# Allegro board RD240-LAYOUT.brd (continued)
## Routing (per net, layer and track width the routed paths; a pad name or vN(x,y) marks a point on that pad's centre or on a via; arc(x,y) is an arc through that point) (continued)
LGND: length 528.6
  TOP w0.3: v1(244.3,6.5) 244.88,6.5 R208.1 ; 193.43,130.2 194.01,130.2 194.13,130.32 v1(194.63,130.32) ; R70.1 247.7,11.18 v1(247.7,12.1) ; 233.2,53.42 233.2,52.44 ; 233.2,53.42 232.53,53.42 ; 233.2,53.42 233.21,53.42 233.67,53.88 234.74,53.88 235.1,54.24 v2(235.1,57.45) ; 229.66,68.86 229.87,69.22 v1(230.1,69.55) ; v1(236.73,14.61) 236.73,15.78
  TOP w0.45: R25.1 232.53,53.42 ; 226.95,102.01 226.95,103.31 ; C61.1 227.72,105.4 226.95,104.63 226.95,104.09 ; 236.73,15.78 C818.1
  TOP w0.5: 255.82,9.9 255.82,6.1 ; 255.82,11.9 255.82,17.7
  TOP w0.55: 229.66,68.16 229.66,68.86 ; D29.A 233.2,52.44
  TOP w0.72: 193.43,130.2 R805.1
  TOP w0.92: 226.95,103.31 C88.1 226.95,104.09 ; C89.1 226.95,102.01
  TOP w1: 302.5,88 C6.1 ; C6.1 300.5,90 ; C6.1 300.5,86.85 ; C3.1 292.5,129.5 ; C3.1 291,128 ; C3.1 294,128 ; C5.1 301.5,99 ; C5.1 303.5,100.5 ; C5.1 301.5,102.5 ; 301.5,114.5 C4.1 ; C4.1 304,112.5 ; C4.1 301.5,110.5 ; 220.75,21.82 220.75,24.73 v1(220.05,25.43) ; 278.5,128 C2.1 ; C2.1 280.5,130 ; C2.1 282.5,128
  TOP w1.5: CN9.2 272.46,127.99 ; CN8.2 266.41,128.09
  TOP w1.6: C816.1 220.75,21.82
  TOP w2.3: v3(297.5,32.5) CN7.1 ; v3(297.5,32.5) 302.25,32.5 ; v3(297.5,32.5) 294.05,32.5 ; v3(297.5,32.5) 297.5,37.1 ; CN7.1 303,26 ; CN7.1 297.5,20.85 ; CN7.1 293.1,26 ; v3(281.5,26) v3(281.5,32.5) ; v3(281.5,26) 281.5,22.7 ; v3(281.5,26) 278.3,26 ; v3(281.5,26) 284.6,26 ; v3(281.5,32.5) 277.65,32.5 ; v3(281.5,32.5) 281.5,37.65 ; v3(281.5,32.5) 285,32.5
  CONDUCTIVE2 w0.3: v1(194.63,130.32) 196.09,130.32
  CONDUCTIVE2 w1: CN9.2 272.46,127.02 ; CN9.2 274.21,125.27 ; CN9.2 272.46,123.52 ; CN8.2 266.41,127.02 ; CN8.2 266.41,123.52 ; CN8.2 268.16,125.27 ; C3.1 294.2,128 ; C3.1 292.5,126.3 ; C3.1 290.8,128 ; C3.1 292.5,129.7 ; CN10.2 268.3,16.84 ; CN10.2 271.3,16.84 ; CN10.2 269.8,18.34 ; TP42.1 265.7,5.3 ; TP42.1 267.4,7 ; TP42.1 265.7,8.7 ; TP42.1 264,7 ; C6.1 302.2,88 ; C6.1 300.5,86.3 ; C6.1 298.8,88 ; C6.1 300.5,89.7 ; C5.1 301.5,98.8 ; C5.1 301.5,102.2 ; C5.1 299.8,100.5 ; C5.1 303.2,100.5 ; C2.1 280.5,129.7 ; C2.1 278.8,128 ; C2.1 280.5,126.3 ; C2.1 282.2,128 ; C4.1 301.5,114.2 ; C4.1 301.5,110.8 ; C4.1 303.2,112.5 ; C4.1 299.8,112.5 ; TP41.1 301.3,121.1 ; TP41.1 303,122.8 ; TP41.1 303,119.4
  CONDUCTIVE2 w2.3: CN7.1 v3(297.5,32.5) ; CN7.1 297.5,22.05 ; CN7.1 293.4,26 ; CN7.1 300.4,26 ; v3(297.5,32.5) 301.65,32.5 ; v3(297.5,32.5) 293.75,32.5 ; v3(297.5,32.5) 297.5,36.9 ; v3(281.5,26) v3(281.5,32.5) ; v3(281.5,26) 281.5,22.1 ; v3(281.5,26) 277.05,26 ; v3(281.5,26) 285.4,26 ; v3(281.5,32.5) 281.5,37.25 ; v3(281.5,32.5) 277.6,32.5 ; v3(281.5,32.5) 285.75,32.5
  CONDUCTIVE5 w0.3: v1(194.63,130.32) 196.87,130.32
  CONDUCTIVE5 w1: CN10.2 271.3,16.84 ; CN10.2 268.3,16.84 ; CN10.2 269.8,18.34 ; TP42.1 265.7,5.3 ; TP42.1 264,7 ; TP42.1 267.4,7 ; TP42.1 265.7,8.7 ; C2.1 280.5,126.3 ; C2.1 282.2,128 ; C2.1 280.5,129.7 ; C2.1 278.8,128 ; C4.1 301.5,114.2 ; C4.1 299.8,112.5 ; C4.1 301.5,110.8 ; C4.1 303.2,112.5 ; TP41.1 303,119.4 ; TP41.1 303,122.8 ; TP41.1 304.45,121.1 ; TP41.1 301.3,121.1 ; C3.1 292.5,126.3 ; C3.1 292.5,129.7 ; C3.1 290.8,128 ; C3.1 294.2,128 ; C6.1 300.5,86.3 ; C6.1 298.8,88 ; C6.1 300.5,89.7 ; C6.1 302.2,88 ; C5.1 301.5,98.8 ; C5.1 299.8,100.5 ; C5.1 303.2,100.5 ; C5.1 301.5,102.2 ; CN9.2 272.46,123.52 ; CN9.2 272.46,127.02 ; CN9.2 274.21,125.27 ; CN8.2 266.41,123.52 ; CN8.2 268.16,125.27 ; CN8.2 266.41,127.02
  CONDUCTIVE5 w2.3: CN7.1 297.5,20.65 ; CN7.1 301.3,26 ; CN7.1 292.3,26 ; CN7.1 v3(297.5,32.5) ; v3(281.5,32.5) 276.65,32.5 ; v3(281.5,32.5) 284.95,32.5 ; v3(281.5,32.5) v3(281.5,26) ; v3(281.5,32.5) 281.5,38.35 ; v3(297.5,32.5) 297.5,37.1 ; v3(297.5,32.5) 293.05,32.5 ; v3(297.5,32.5) 301.25,32.5 ; v3(281.5,26) 281.5,21.95 ; v3(281.5,26) 285.35,26 ; v3(281.5,26) 278.05,26
  BOTTOM w0.3: 234.38,5.75 235.47,5.75 R829.1 ; 235.32,5.72 234.2,5.72 ; 231.56,10.75 231.95,10.75 v1(232.2,11) ; v1(245.25,68.95) 245.25,69.67 R22.1 ; v1(227.53,100.01) v1(226.76,100.01) 226.76,101.66 D26.A ; R43.1 259.27,14.5 v1(258.4,14.5) 257.68,14.5 257.4,14.22 ; 234.38,8.78 235.38,8.78 ; 235.68,5.72 v1(236.54,5.72) ; 235.68,8.72 v1(236.54,8.72) ; v1(260.2,5.4) 259.2,5.4 ; 260,16.2 v1(261,16.2) ; 235.32,8.72 234.2,8.72
  BOTTOM w0.45: 259.2,5.4 259.02,5.4 ; IC12.2 231.04,10.41 C104.1 231.56,10.75 ; 234.2,8.78 234.38,8.78 ; R45.1 260,16.2 ; 235.32,8.72 R821.1 235.68,8.72 ; 235.32,5.72 R829.1 235.68,5.72 ; R825.1 234.38,5.75 ; v1(268.1,35.3) 268.11,35.31 268.11,36.55
  BOTTOM w0.5: T4.3 215.6,44.42 ; TP42.1 266.75,5.95 ; R21.1 237.38,104.55 v1(235.3,104.55) ; CN10.2 269.8,17.85 ; v1(220.05,25.43) 218.28,27.2 R9.1 ; v1(244.3,9.3) R66.1 ; v1(244.3,6.5) R64.1 ; v2(235.1,122.6) 233.6,122.6 233.15,122.15 D27.A ; v1(253.7,5.1) R54.1
  BOTTOM w0.825: IC8.4 268.11,36.55
  BOTTOM w1: C3.1 292.5,129.5 ; C3.1 292.5,126.3 ; C3.1 294,128 ; C3.1 291,128 ; 214.85,16 215.9,16 R812.1 ; C6.1 300.5,86 ; C6.1 300.5,90 ; C6.1 298.5,88 ; C6.1 302.5,88 ; C5.1 301.5,98.5 ; C5.1 301.5,102.5 ; C5.1 300,100.5 ; C5.1 303.5,100.5 ; C2.1 282.5,128 ; C2.1 278.5,128 ; C2.1 280.5,130 ; C2.1 280.5,126 ; C4.1 301.5,110.5 ; C4.1 303.5,112.5 ; C4.1 300,112.5 ; C4.1 301.5,114.5
  BOTTOM w2.3: CN7.1 292.3,26 ; CN7.1 v3(297.5,32.5) ; CN7.1 297.5,21.4 ; CN7.1 302,26 ; v3(281.5,26) 278.8,26 ; v3(281.5,26) v3(281.5,32.5) ; v3(281.5,26) 281.5,21.7 ; v3(281.5,26) 286.05,26 ; v3(297.5,32.5) 301.3,32.5 ; v3(297.5,32.5) 293.65,32.5 ; v3(297.5,32.5) 297.5,36.6 ; v3(281.5,32.5) 281.5,35.8 ; v3(281.5,32.5) 278.95,32.5 ; v3(281.5,32.5) 286.15,32.5
  vias: v1(232.92,2.65) v1(233.35,60.85) v1(234.6,60.85) v1(235.2,17.02) v1(249.34,17.25) v1(252.9,17.3) v1(257,11.2) v1(260.05,8.9) v1(269.5,35.3) v1(304.5,80) v1(304.5,74.6) v1(304.5,70) v1(304.5,65) v1(304.5,60) v1(304.5,55) v1(304.5,51.8) v1(304.5,48.55) v2(227.85,89.85) v2(227.85,87.75) v2(229.95,89.85) v2(229.95,87.75) v2(229.95,85.65) v2(235.05,128.5) v2(235.3,114) v2(235.3,111.9) v2(235.3,109.8) v2(235.3,67.35) v2(235.3,65.25) v2(235.3,63.15) v2(235.4,81.8) v2(235.4,79.7) v2(235.4,76.7) v2(236.25,130.6) v2(236.35,59.15) v2(236.7,68.95) v2(237.15,128.5) v2(237.2,122.6) v2(237.4,114) v2(237.4,111.9) v2(237.4,109.8) v2(237.5,81.8) v2(237.5,79.7) v2(237.5,76.7) v2(237.71,57.41) v2(237.77,65.27) v2(237.8,63.15) v2(238.35,130.6) v2(238.8,68.95) v2(239.3,128.5) v2(239.5,116.1) v2(239.5,114) v2(239.5,111.9) v2(239.5,109.8) v2(239.6,81.8) v2(239.6,79.7) v2(240.45,130.6) v2(240.9,68.95) v2(241.7,79.7) v2(242.55,130.6) v2(262,130.5) v2(271,130.5) v2(273,130.5) v2(273,128.5) v2(275,130.5) v2(275.1,36.6) v2(275.1,33.6) v2(275.1,30.6) v2(275.1,27.6) v2(275.1,24.6) v2(275.1,21.6) v2(275.1,18.6) v2(275.1,15.6) v2(277.1,35.1) v2(277.1,32.1) v2(277.1,29.1) v2(277.1,26.1) v2(277.1,23.1) v2(277.1,20.1) v2(277.1,17.1) v2(279.1,42.4) v2(279.1,39.4) v2(279.1,21.6) v2(279.1,18.6) v2(279.1,15.6) v2(281.1,40.9) v2(281.1,37.9) v2(281.1,20.1) v2(281.1,17.1) v2(283.1,42.4) v2(283.1,39.4) v2(283.1,21.6) v2(283.1,18.6) v2(283.1,15.6) v2(284,130.5) v2(285.1,40.9) v2(285.1,37.9) v2(285.1,20.1) v2(285.1,17.1) v2(286,130.5) v2(286,128.5) v2(287.1,42.4) v2(287.1,39.4) v2(287.1,36.4) v2(287.1,21.6) v2(287.1,18.6) v2(287.1,15.6) v2(288,130.5) v2(289.1,40.9) v2(289.1,37.9) v2(289.1,20.1) v2(289.1,17.1) v2(291.1,39.4) v2(291.1,36.4) v2(291.1,21.6) v2(291.1,18.6) v2(291.1,15.6) v2(293.1,40.9) v2(293.1,37.9) v2(293.1,20.1) v2(293.1,17.1) v2(295.1,42.4) v2(295.1,39.4) v2(295.1,36.4) v2(295.1,21.6) v2(295.1,18.6) v2(295.1,15.6) v2(297.1,40.9) v2(297.1,37.9) v2(297.1,20.1) v2(297.1,17.1) v2(297.5,130.5) v2(299,124.4) v2(299.1,42.4) v2(299.1,39.4) v2(299.1,21.6) v2(299.6,121.12) v2(299.9,118.8) v2(301.1,40.9) v2(301.1,37.9) v2(301.1,34.9) v2(301.1,31.9) v2(301.1,28.9) v2(301.1,25.9) v2(301.1,22.9) v2(301.92,124.4) v2(302,118) v2(302,104.5) v2(302,95.5) v2(302,93.5) v2(302,91.5) v2(302,89.5) v2(303.1,39.4) v2(303.1,36.4) v2(303.1,33.4) v2(303.1,30.4) v2(303.1,27.4) v2(303.1,24.4) v2(304,118) v2(304,116) v2(304,106.5) v2(304,104.5) v2(304,102.5) v2(304,93.5) v2(304,91.5) v2(304,89.5)
OUTA1: length 194.6
  TOP w0.3: v1(135.4,121.1) TP38.1 ; 141.66,116.8 141.3,116.8 141.1,117 v1(140.6,117)
  TOP w0.45: 141.66,116.8 141.78,116.8
  CONDUCTIVE3 w0.2: v1(140.6,117) 141.71,117 143.51,115.2 143.51,103 138.18,97.66 138.18,86.11 139.95,84.33 154.56,84.33 163.7,75.18 166.88,75.18 173.3,68.76 173.3,12.65 175.95,10 212.12,10 215.15,6.97 v1(216.97,6.97) ; v1(140.6,115.7) 139.9,116.4 139.9,117.8 136.6,121.1 v1(135.4,121.1)
  BOTTOM w0.5: IC12.14 219.14,9.14 v1(216.97,6.97)
OUTA2: length 47.8
  TOP w0.3: v1(247.8,14.78) 245.34,14.78 241.1,10.54 v1(241.1,9.62) ; v1(265.4,3.5) TP34.1
  CONDUCTIVE3 w0.2: v1(247.8,14.78) 248.28,14.78 249.94,13.12 249.94,8.76 251.59,7.11 259.54,7.11 263.15,3.5 v1(265.4,3.5)
  BOTTOM w0.3: 234.02,9.62 233.17,9.62 R819.1 ; 238.6,9.62 v1(241.1,9.62) ; 230.2,9.14 231.66,9.14 ; IC10.22 v1(247.8,14.78) ; 237.4,9.62 234.38,9.62
  BOTTOM w0.45: 231.66,9.14 R819.2 ; R816.2 238.6,9.62 ; 234.38,9.62 R817.2 234.02,9.62 ; R816.1 237.4,9.62
  BOTTOM w0.55: IC12.3 230.2,9.14
OUTB1: length 201.4
  TOP w0.3: v1(129.1,121.1) TP39.1 ; 141.7,113.4 141.34,113.4 141.14,113.6 v1(140.6,113.6)
  TOP w0.45: 141.7,113.4 141.78,113.4
  CONDUCTIVE3 w0.2: v1(140.6,112.3) 139.5,113.4 139.5,117.6 138.2,118.9 131.3,118.9 v1(129.1,121.1) ; v1(215.79,6.12) 214.99,6.12 211.56,9.55 175.5,9.55 172.7,12.35 172.7,68.47 166.62,74.55 163.19,74.55 154.05,83.69 139.53,83.69 137.59,85.64 137.59,97.83 143,103.24 143,112.21 141.61,113.6 v1(140.6,113.6)
  BOTTOM w0.5: IC12.13 219.17,7.87 217.42,6.12 v1(215.79,6.12)
OUTB2: length 37
  TOP w0.3: v1(247.1,14.12) 245.66,14.12 241.9,10.36 241.9,8.67 v1(241.1,7.87) ; v1(252,3.5) TP35.1
  CONDUCTIVE3 w0.2: v1(252,3.5) 249.17,6.33 249.17,13.15 248.2,14.12 v1(247.1,14.12)
  BOTTOM w0.3: IC10.21 v1(247.1,14.12) ; 235.68,7.87 237.4,7.87 ; 232.87,7.87 235.32,7.87 ; 238.6,7.87 v1(241.1,7.87) ; 230.2,7.87 231.66,7.87
  BOTTOM w0.45: 235.32,7.87 R821.2 235.68,7.87 ; R820.2 238.6,7.87 ; R823.1 232.87,7.87 ; 231.66,7.87 R823.2 ; 237.4,7.87 R820.1
  BOTTOM w0.55: IC12.4 230.2,7.87
OUTC1: length 120.5
  TOP w0.3: R113.1 156.82,66.55 157.83,66.55 159.06,67.78 162.9,67.78 v1(163.38,68.25)
  CONDUCTIVE3 w0.2: v1(216.28,4.95) 215.26,4.95 211.62,8.6 174.6,8.6 171.45,11.75 171.45,35.12 163.38,43.2 v1(163.38,68.25)
  BOTTOM w0.5: v1(216.28,4.95) 216.68,5.35 217.9,5.35 219.15,6.6 IC12.12
OUTC2: length 44.8
  TOP w0.3: v1(258.7,3.5) TP36.1 ; v1(247.8,13.47) 245.94,13.47 242.59,10.12 242.59,8.09 v1(241.1,6.6)
  CONDUCTIVE4 w0.3: v1(258.7,3.5) 257.63,2.43 243.8,2.43 242.65,3.58 242.65,5.05 v1(241.1,6.6)
  BOTTOM w0.3: IC10.20 v1(247.8,13.47) ; 232.87,6.6 234.02,6.6 ; 230.2,6.6 231.66,6.6 ; 234.38,6.6 237.4,6.6 ; 238.6,6.6 v1(241.1,6.6)
  BOTTOM w0.45: R827.1 232.87,6.6 ; 231.66,6.6 R827.2 ; 237.4,6.6 R824.1 ; 234.02,6.6 R825.2 234.38,6.6 ; R824.2 238.6,6.6
  BOTTOM w0.55: IC12.5 230.2,6.6
OUTD1: length 133.7
  TOP w0.3: v1(162.88,69.4) 162.88,68.83 162.43,68.38 158.81,68.38 158.01,67.58 157.24,67.58
  TOP w0.45: R112.1 157.24,67.58
  CONDUCTIVE3 w0.2: v1(217.9,4.35) 216.89,4.35 216.28,3.74 215.51,3.74 211.15,8.1 174.1,8.1 170.75,11.45 170.75,34.95 162.63,43.07 162.63,69.16 v1(162.88,69.4)
  CONDUCTIVE4 w0.2: v1(152.8,76.15) 152.8,74.13 155.85,71.08 159.45,71.08 160.78,69.75 v1(160.78,69.1)
  BOTTOM w0.5: IC12.11 219.23,5.33 218.25,4.35 v1(217.9,4.35)
OUTD2: length 30.4
  TOP w0.3: v1(247.1,12.82) 246.25,12.82 243.2,9.77 243.2,6.97 v1(241.1,4.88) 244.38,1.6 246,1.6
  TOP w2.1: 246,1.6 TP37.1
  BOTTOM w0.3: 230.2,5.33 231.66,5.33 ; 235.32,4.88 233.15,4.88 R831.1 ; 238.6,4.88 v1(241.1,4.88) ; IC10.19 v1(247.1,12.82) ; 235.68,4.88 237.4,4.88
  BOTTOM w0.45: 235.32,4.88 R829.2 235.68,4.88 ; R828.2 238.6,4.88 ; 231.66,5.33 R831.2 ; 237.4,4.88 R828.1
  BOTTOM w0.55: IC12.6 230.2,5.33
OUTE: length 131.5
  TOP w0.3: v1(251,12) 251,19.73 250.55,20.18 250.55,22.36
  TOP w2.1: 250.55,22.36 TP23.1
  CONDUCTIVE4 w0.2: v1(251,12) 251,13.92 246.52,18.4 232.05,18.4 225.65,24.8 225.65,52.37 230.75,57.47 230.75,65.65 v1(231.7,66.6) 231.05,67.25 229.45,67.25 228.25,68.45 228.25,84.1 225.25,87.1 225.25,88.55 235.25,98.55 v1(235.25,103.2)
OUTF: length 135.2
  TOP w0.3: 244.7,22.31 244.7,19.27 249.49,14.48 249.49,12.26 v1(251,10.75)
  TOP w2.1: 244.7,22.31 TP24.1
  CONDUCTIVE4 w0.2: v1(234.2,103.9) 234.2,98.1 224.85,88.75 224.85,86.9 227.85,83.9 227.85,68.05 v1(229.3,66.6) 230.35,65.55 230.35,57.73 225.25,52.63 225.25,24.6 231.85,18 246.29,18 250.06,14.22 250.03,14.19 250.03,11.72 v1(251,10.75)
PN: length 476.1
  TOP w0.3: v1(140.6,118.2) 141.6,118.2 ; v1(127.8,57.1) 126.4,57.1 ; v1(140.6,114.6) 140.8,114.8 141.6,114.8 ; v1(155.7,50.9) 156.7,50.9
  TOP w0.45: 141.6,114.8 141.78,114.8 ; C35.1 151.2,49.3 150.9,49.6 v1(150.3,49.6) ; 156.7,50.9 R71.1 ; v1(130.4,51.6) 133.18,51.6 ; 141.6,118.2 141.78,118.2 ; C62.1 v1(147.9,53.6) ; 126.4,57.1 R73.1
  TOP w0.5: v1(178.44,123.95) 178.44,123.64 177.95,123.15 R224.1 ; v1(150.3,51.9) 149.57,51.9 ; v1(130.9,70.5) 130.62,70.78 129.6,70.78 ; R223.1 173.53,99.2 v1(172.64,99.2) ; R225.1 83.08,129.72 v1(82.87,129.93) ; v1(150.3,49.6) 149.57,49.6 ; R221.1 167.3,47.17
  TOP w0.92: 149.57,51.9 C82.1 ; 149.57,49.6 C83.1
  TOP w1: 203.45,16 198.87,16 C800.1
  CONDUCTIVE2 w1: 203.45,16 203.45,14.45 ; 203.45,16 201.9,16 ; 203.45,16 205,16 ; Q6.S v1(166.28,129.8) 166.28,129.5 ; Q6.S 168.21,131.3 ; Q6.S 164.82,131.3 ; IC20.1 84.75,71.29 ; C800.1 187.56,6.38 ; C800.1 189.25,4.69 ; C800.1 189.25,8.07 ; C800.1 190.94,6.38 ; C7.1 133.02,26.8 ; C7.1 129.5,30.14 ; C7.1 129.5,23.46 ; C7.1 125.78,26.8 ; D3.4 124.7,129.32 ; D3.4 122.71,130.98 ; D3.4 124.7,132.43 ; D3.4 126.87,130.98 ; Q2.S v1(142.82,63.65) 142.82,63.95 ; Q2.S 144.25,62.15 ; Q2.S 141.02,62.15 ; Q2.S 142.82,60.35 ; Q4.S 159.92,85.7 ; Q4.S 158.12,87.5 ; Q4.S 161.24,87.5 ; Q4.S v1(159.92,89) 159.92,89.3 ; Q1.S 111.62,60.35 ; Q1.S v1(111.62,63.65) 111.62,63.95 ; Q1.S 109.82,62.15 ; Q1.S 112.87,62.15 ; 109.3,70.2 T3.2 111.1,68.4 ; C1.1 160.65,28.49 ; C1.1 157.03,25.15 ; C1.1 160.65,21.66 ; C1.1 164.56,25.15 ; 134.6,68.4 T2.2 132.8,70.2 ; TP45.1 177.9,3.7 ; TP43.1 125,3.6
  CONDUCTIVE3 w0.2: v1(105.6,84.9) 106.7,83.8 121.4,83.8 122.75,82.45 122.75,66.5 124.6,64.65 124.6,53.3 132.28,45.62 149.05,45.62 152.6,42.08 152.6,28.6 153.6,27.6 153.6,4.15 v1(152.8,3.35) ; v1(126.6,82.4) 126.45,81.94 126.45,60.15 128.8,57.8 131.9,57.8 142.3,47.4 149.2,47.4 156.2,40.4 156.2,30.05 156.68,29.57 156.68,4.98 v1(155.7,4)
  CONDUCTIVE5 w1: D3.4 124.7,132.38 ; D3.4 122.28,130.98 ; D3.4 124.7,129.21 ; D3.4 126.68,130.98 ; 132.8,70.2 T2.2 134.6,68.4 ; TP45.1 177.9,3.7 ; Q6.S v1(166.28,129.8) 166.28,129.5 ; Q6.S 164.92,131.3 ; Q6.S 168.36,131.3 ; C1.1 160.65,28.49 ; C1.1 160.65,21.81 ; C1.1 163.99,25.15 ; C1.1 157.31,25.15 ; 159.92,89.3 v1(159.92,89) Q4.S ; C7.1 129.5,23.46 ; C7.1 132.84,26.8 ; C7.1 126.16,26.8 ; C7.1 129.5,30.14 ; Q2.S v1(142.82,63.65) 142.82,63.95 ; Q2.S 141.02,62.15 ; Q2.S 142.82,60.35 ; Q2.S 144.15,62.15 ; 203.45,16 205,16 ; 203.45,16 203.45,14.45 ; 203.45,16 201.9,16 ; Q4.S 158.12,87.5 ; Q4.S 159.92,85.7 ; Q4.S 161.35,87.5 ; C800.1 189.25,4.69 ; C800.1 187.56,6.38 ; C800.1 189.25,8.07 ; C800.1 190.94,6.38 ; Q1.S 111.62,60.35 ; Q1.S 113,62.15 ; Q1.S 109.82,62.15 ; Q1.S v1(111.62,63.65) 111.62,63.95 ; TP43.1 125,3.6 ; 109.3,70.2 T3.2 111.1,68.4 ; IC20.1 84.91,71.45
  BOTTOM w0.3: C1.1 156.6,25.15 ; 214.9,4.96 214.3,4.96 213.53,4.19 211.02,4.19 ; C7.1 126.7,24 ; v1(105.6,84.9) 105.12,85.38 103.81,85.38 103.54,85.65 103.54,86.32
  BOTTOM w0.45: v1(187.71,13.24) 187,13.95 ; R806.1 R807.1 ; 214.9,4.96 C67.1
  BOTTOM w0.5: 219.94,10.4 v1(221.54,10.4) ; TP43.1 125,9.3 133,17.3 135.68,17.3
  BOTTOM w0.55: IC11.2 211.02,4.19
  BOTTOM w0.895: 103.54,86.32 R7.1
  BOTTOM w1: IC20.1 84,70.54 ; TP45.1 179.4,2 ; C800.1 189.25,4.85
  BOTTOM w1.405: 135.68,17.3 R179.1
  BOTTOM w1.5: 203.45,16 204.85,16
  vias: v1(110.62,63.65) v1(112.62,63.65) v1(120.4,52.8) v1(140.4,3.45) v1(141.1,110.5) v1(141.1,109.2) v1(141.1,107.9) v1(141.82,63.65) v1(142.75,98.05) v1(142.75,96.8) v1(143.82,63.65) v1(144.4,3.25) v1(144.7,51.8) v1(145.9,7.55) v1(146.5,13.15) v1(151.29,14.99) v1(151.7,9.85) v1(153.5,75.45) v1(155.9,112.1) v1(155.9,110.8) v1(158.92,89) v1(160.92,89) v1(161.82,69.1) v1(164.18,69.28) v1(165.28,129.8) v1(166.1,69.85) v1(166.1,68.6) v1(167.28,129.8) v1(167.3,47.2) v1(175.18,26.9) v1(175.18,26.15) v1(175.26,18.29) v1(175.26,16.76) v1(208.5,4.2) v1(218.28,2.08)
SIG6: length 54.1
  TOP w0.3: 120.69,124.85 119.65,124.85 117.2,127.3 D3.3
  TOP w1.2: 120.69,124.85 D9.A
  BOTTOM w1: IC20.3 92.11,49.47 ; C33.1 74.39,125.15 ; R138.1 98.52,50.48
  BOTTOM w1.5: C64.2 117.22,11.9
  BOTTOM w5: D3.3 117.2,117.9 117.9,117.2 117.9,102.5 ; L12.1 104.88,32.2 ; 109.29,123.09 109.29,130.97
  vias: v1(76.71,93.09) v1(129.1,63.81) v1(130.1,63.81) v1(131.1,63.81) v1(160.3,63.81) v1(161.3,63.81)
SIG15: length 1.3
  BOTTOM w0.3: 129,84.28 129,83.6
  BOTTOM w0.55: D12.A 129,84.28
SIG18:
  vias: v1(147.26,63.65) v1(148.26,63.65) v1(149.26,63.65)
SIG20: length 2.1
  BOTTOM w0.3: 105.92,84.05 105.92,83.28 106.4,82.8 106.8,82.8
  BOTTOM w0.45: C36.2 105.92,84.05 ; 106.8,82.8 R85.1
SIG22:
  vias: v1(116.06,63.65) v1(117.06,63.65) v1(118.06,63.65)
SIG23:
  vias: v1(153.7,63.65)
SIG27: length 6.8
  TOP w0.3: Q1.G 122.5,55.67
  TOP w1.17: 122.5,55.67 FB2.2
  vias: v1(122.5,63.65)
SIG47: length 6.2
  BOTTOM w0.35: 149.29,14.47 148.5,14.47 147.5,15.47 R93.2 ; 147.74,11.91 148.67,11.91 149.4,12.64 149.4,13.44
  BOTTOM w0.45: C41.2 149.4,13.44 ; 149.29,14.47 C41.1
  BOTTOM w0.72: 147.74,11.91 C40.2
SIG0052: length 53.8
  TOP w0.3: v1(246.8,122.24) 246.04,123 241.94,123 ; v1(233.45,120.3) 233.45,119.16 233.47,118.79
  TOP w0.5: 233.47,118.79 Q13.4
  TOP w2.1: 241.94,123 TP19.1
  CONDUCTIVE3 w0.3: v1(246.8,122.24) 244.06,119.5 234.25,119.5 v1(233.45,120.3)
  CONDUCTIVE4 w0.6: v1(233.45,120.3) v1(233.45,113.6) 233.45,109.75 234.9,108.3 236.85,108.3 v1(237.15,108) 237.15,102.8 v1(239,100.95)
  BOTTOM w0.3: 233.44,101.8 234.73,101.8 ; R213.2 238.72,101.8 R21.2 ; 234.5,99.5 236.11,99.5 ; 239,99.89 v1(239,100.95) 239,101.9
  BOTTOM w0.45: 239,101.9 R21.2
  BOTTOM w0.8: 233.44,101.8 D54.A 233.22,101.8
  BOTTOM w0.92: 236.11,99.5 R20.1 ; R20.2 239,99.89 ; 234.73,101.8 R213.1
  BOTTOM w1.1: D53.C 234.5,99.5
SIG53: length 1.1
  BOTTOM w0.45: R176.2 155.5,5.56 R101.2
SIG0053: length 42.8
  TOP w0.3: v1(233.5,126.3) 233.47,125.89 233.47,125.42 ; v1(234.7,131.05) 234.44,131.31 233.88,131.31 ; v1(213.1,129.6) TP21.1
  TOP w0.5: Q12.4 233.47,125.42 ; Q11.4 233.88,131.31
  CONDUCTIVE4 w0.2: v1(213.1,129.6) 215.05,131.55 234.2,131.55 v1(234.7,131.05)
  CONDUCTIVE4 w0.6: v1(238.3,121.3) 234.35,121.3 233.5,122.15 v1(233.5,126.3) 233.5,129.85 v1(234.7,131.05)
  BOTTOM w0.3: v1(233.5,126.3) 233.5,126.9 233.47,126.92 Q25.4
  BOTTOM w0.5: Q25.4 233.8,127.5
SIG54: length 1.1
  BOTTOM w0.45: R175.2 R102.2
SIG0054: length 38.4
  TOP w0.3: 233.47,81.39 233.47,81.95 233.22,82.2 v1(231.6,82.2)
  TOP w0.5: 233.47,81.39 Q7.4
  CONDUCTIVE4 w0.6: v1(225.95,87.95) 225.95,87.85 v1(231.6,82.2) 231.6,80.4 233.87,78.13 v1(235.37,78.13) 242.62,78.13 v1(243.85,76.9) 244.9,75.85 244.9,69.89 v1(243.96,68.95)
  BOTTOM w0.3: v1(225.95,87.95) 225.97,88.36 225.97,89.11 ; v1(235.37,78.13) 234.83,78.13 234.09,77.39 233.72,77.39
  BOTTOM w0.5: Q8.4 225.97,89.11
SIG0055: length 60.7
  TOP w0.3: 233.47,75.39 233.5,75.76 v1(233.5,76.25) ; v1(233.5,54.75) 232.14,54.75 231.5,54.11 231.5,53.45 ; 231.32,53.42 v1(229.55,53.42)
  TOP w0.45: 231.32,53.42 R25.2 231.5,53.45
  TOP w0.5: 233.47,75.39 Q27.4
  CONDUCTIVE4 w0.6: v1(233.5,54.75) 233.5,58.05 v1(236.25,60.8) 236.25,61.4 235.75,61.9 234.75,61.9 234.05,62.6 234.05,69.05 235.25,70.25 242.8,70.25 v1(243.85,71.3) 243.85,72.35 242.15,74.05 234.6,74.05 233.5,75.15 v1(233.5,76.25)
  BOTTOM w0.3: 228,52.03 228,52.77 228.65,53.42 v1(229.55,53.42) ; 233.92,61.8 235.25,61.8 v1(236.25,60.8) ; 228,47.64 228,49.02 ; 230.3,48.98 230.3,47.37 ; v1(233.5,54.75) 233.47,55.16 233.47,55.66 ; 228.61,51.95 229.91,51.95
  BOTTOM w0.5: Q9.4 233.47,55.66
  BOTTOM w0.55: Q10.4 233.92,61.8
  BOTTOM w0.8: D58.A 228,47.64
  BOTTOM w0.92: R24.1 230.3,48.98 ; 228.61,51.95 R215.2 228,52.03 ; 229.91,51.95 R24.2 ; 228,49.02 R215.1
  BOTTOM w1.1: 230.3,47.37 D57.C
SIG82:
  vias: v1(155.4,129.8)
SIG86: length 2.2
  BOTTOM w0.3: 136.25,5.76 137.98,5.76
  BOTTOM w0.45: R120.2 136.25,5.76
  BOTTOM w1.2: 137.98,5.76 D49.C
SIG91: length 2.3
  TOP w0.92: C85.2 170.2,71.25
  BOTTOM w0.3: v1(165.1,71.88) 165.1,72.29 165.05,73.11
  BOTTOM w1.1: 165.05,73.11 D17.A
SIG95:
  vias: v1(153.2,108.8)
SIG116: length 25
  CONDUCTIVE4 w0.6: v1(233.5,47.81) 233.5,53.45 232,54.95 232,65.65 v1(232.95,66.6)
  BOTTOM w0.3: v1(233.5,47.81) 233.5,46.36 232.14,45 230.45,45
  BOTTOM w0.8: D57.A 230.45,45
SIG117:
  vias: v1(228.95,69.55)
SIG121: length 1.7
  TOP w0.45: 229.66,62.28 229.66,61.31 229.68,61.3
  TOP w0.55: 229.66,63.04 229.66,62.28
SIG124: length 4.2
  TOP w0.3: 229.18,99.83 229.18,100.92 C89.2
  TOP w0.45: 229.18,99.83 229.18,99.65 ; 229.65,102.01 229.65,103.31
  TOP w0.92: 229.65,103.31 C88.2 ; C89.2 229.65,102.01
SIG126: length 9.9
  BOTTOM w0.3: 232.1,99.64 232.1,101.05 D54.C ; 229.66,102.7 229.95,102.7 230.2,102.95 v1(233.15,102.95) ; 228.95,102.51 228.95,102.1 229.25,101.8 230.57,101.8
  BOTTOM w0.55: 228.95,102.51 D26.C 229.66,102.7
  BOTTOM w0.8: D53.A 232.1,99.64
  BOTTOM w1.1: 231.22,101.8 230.57,101.8
SIG127: length 9.6
  CONDUCTIVE4 w0.6: v1(231.85,113.6) 231.85,105.75 v1(233.1,104.5)
SIG135: length 1.8
  TOP w2: TP30.1 219.9,129.6
SIG136: length 84.2
  TOP w0.3: 286.1,78.98 v1(286.1,80) ; 273.1,78.98 v1(273.1,80) ; 279.6,78.98 v1(279.6,80) ; v1(268.1,46.15) 268.1,47.6 268.7,48.2 270.27,48.2 ; 292.6,78.98 v1(292.6,80) ; 299.1,78.98 v1(299.1,80)
  TOP w0.5: Q17.4 286.1,78.98 ; Q15.4 299.1,78.98 ; Q18.4 279.6,78.98 ; Q16.4 292.6,78.98 ; Q19.4 273.1,78.98
  TOP w2.1: 270.27,48.2 TP28.1
  CONDUCTIVE4 w0.2: v1(299.1,80) v1(292.6,80) v1(286.1,80) v1(279.6,80) v1(273.1,80) 271.2,78.11 271.2,49.25 v1(268.1,46.15)
  BOTTOM w0.3: v1(286.1,80) 285.9,79.81 285.9,78.98 ; v1(292.6,80) 292.4,79.81 292.4,78.98 ; v1(299.1,80) 298.9,79.81 298.9,78.98 ; v1(279.6,80) 279.4,79.81 279.4,78.98 ; 272.9,78.98 272.9,79.81 v1(273.1,80)
  BOTTOM w0.45: v1(268.1,46.15) R6.2 ; 268.1,43.69 268.1,43.15 268.11,42.64
  BOTTOM w0.5: 279.4,78.98 Q23.4 ; 272.9,78.98 Q24.4 ; 285.9,78.98 Q22.4 ; 292.4,78.98 Q21.4 ; 298.9,78.98 Q20.4
  BOTTOM w0.72: R6.1 268.1,43.69
  BOTTOM w0.825: 268.11,42.64 IC8.5
SIG138: length 17.9
  TOP w0.3: v1(206.5,129.6) TP27.1
  CONDUCTIVE3 w0.2: v1(206.5,129.6) 207.13,128.97 ; R77.2 242.51,125.61
  BOTTOM w2: 234.85,124.6 242.4,124.6 ; 237.05,106.1 243.2,106.1
SIG148:
  vias: v1(252.7,12.2)
SIG149:
  vias: v1(253.7,12.2)
SIG150:
  vias: v1(252.7,10.8)
SIG152: length 29.7
  CONDUCTIVE4 w0.2: v1(252.7,13.5) 252.7,14.75 250.85,16.6 250.85,19.55 251.6,20.3 260.45,20.3 266.45,14.3 CN10.1
  BOTTOM w0.5: CN10.1 270.6,13.5
SIG156: length 29.9
  TOP w0.3: v1(278.8,3.5) TP33.1 ; v1(272.1,3.5) TP32.1
  CONDUCTIVE3 w0.2: v1(253.7,14.2) 255.95,14.2 259.35,10.8 259.35,8.25 262.8,4.8 270.8,4.8 v1(272.1,3.5)
  BOTTOM w0.3: 259,12.28 259.27,12 260.2,12 ; C21.2 258.82,13.3
  BOTTOM w0.45: 260.2,12 R47.1
SIG185: length 1.3
  BOTTOM w0.3: R117.1 214.59,3.62 C67.2
SIG193: length 25.2
  BOTTOM w5: CN1.1 19.7,53.6 32.1,66 F1.1
SIG199: length 44.6
  BOTTOM w1.5: C32.2 L11.1
  BOTTOM w5: 88.4,10.7 88.4,17 84.65,20.75 79.5,20.75 ; 79.2,20.75 74.25,20.75 70.3,16.8 70.3,10
SIG205: length 3.4
  TOP w0.3: 154.75,94.6 155.59,93.26 156,92.85
  TOP w2.1: TP12.1 154.75,94.6
  vias: v1(170.8,89)
SIG223: length 7.5
  CONDUCTIVE3 w0.3: v1(208.5,5.28) 209.42,5.28 210.1,4.6 v1(210.1,1.9)
  BOTTOM w0.45: 210.31,5.31 210.31,6.92 209.89,7.34 R116.2
  BOTTOM w0.825: IC11.3 210.31,5.31
SIG00817: length 5.5
  TOP w0.5: HS1.1 R220.2
SIG00820: length 6.7
  TOP w0.5: R223.2 173.7,95.4 HS4.1
SIG00821: length 25.1
  BOTTOM w0.3: 174.1,28.95 174.1,30.32 175.18,31.4 181.45,31.4 181.85,31 181.85,30.2 ; 177.04,23.7 177.04,24.52 179.55,27.02 179.55,28.7
  BOTTOM w0.45: R811.2 176.03,24.76 ; R810.1 177.04,23.7
  BOTTOM w0.5: 181.85,28.36 181.85,24.35
  BOTTOM w0.55: D84.C 174.1,28.95
  BOTTOM w1: 179.55,28.7 IC81.1 ; 181.85,30.2 IC81.2 181.85,28.36
  BOTTOM w2.25: 181.85,24.35 IC81.4
SIG00822:
  vias: v1(176.6,20.25) v1(176.75,26.75) v1(177.35,20.25) v1(185.1,31.15) v1(185.25,30.25)
SIG00828: length 1.3
  TOP w0.5: v1(183.4,15.6) 182.08,15.6
  vias: v1(184.8,12.25) v1(184.8,11.5)
SIG00831: length 5.1
  TOP w0.5: v1(185,14.8) 184.51,14.31 182.08,14.31
  BOTTOM w0.45: v1(185,14.8) 187,14.8
SIG00832: length 2.7
  TOP w0.5: R803.2 R804.2 176.57,14.22 IC80.4
SIG00834: length 22.6
  TOP w1: T8.3 196.9,19.25 194.9,17.25 186.77,17.25 185.9,18.12 182.08,18.12
SIG00840:
  vias: v1(225.2,18.96) v1(225.9,18.96)
SIGN269: length 2.6
  TOP w0.3: 151.6,122.05 151.15,122.05 151,121.9 149.49,121.9
  TOP w0.55: 151.6,122.05 D23.C
  TOP w0.8: D42.A 149.49,121.9
SIGN322: length 8
  TOP w0.3: 147.27,112.06 147.93,112.06 150.49,109.5 152.8,109.5 v1(153.2,109.9)
  TOP w0.55: IC5.6 147.27,112.06
SIGN355: length 35.9
  BOTTOM w1: 150,99.4 149.05,98.45 ; 150,99.4 149.05,100.35 ; 150,99.4 149.05,99.4 147.95,100.5
  BOTTOM w3: 147.95,102.65 145.85,104.75 145.85,120.35 142.95,123.25 ; 142.94,123.26 v1(142.94,129.8) Q5.D
  vias: v1(141.94,129.8) v1(143.94,129.8) v1(146.96,89) v1(147.96,89) v1(148.96,89)
SIGN360: length 10.9
  TOP w2.5: 242.05,42.5 L5.S 242.05,31.55
SIGN362: length 23.1
  TOP w2.5: 246.55,83.15 L6.S 246.55,94.53
  BOTTOM w2.5: 246.55,83.15 L6.S 246.55,94.87
VREF_PFC: length 9.8
  CONDUCTIVE3 w0.5: v1(149.5,3.65) 148.05,3.65 146.7,5 v1(141.4,5)
  BOTTOM w0.45: 148.17,2.02 149.3,2.02
  vias: v1(144.43,17.27)

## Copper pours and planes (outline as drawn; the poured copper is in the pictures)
P12V on BOTTOM: outline of 90 points within 268.77,34.67 304,76.9 ; 18 cut-outs
P12V on CONDUCTIVE3: 272.4,76.8 272.43,76.87 272.5,76.9 300.24,76.9 300.3,76.89 300.34,76.86 301.86,75.34 301.89,75.29 301.9,75.24 301.9,49.76 301.89,49.7 301.86,49.66 300.24,48.04 300.19,48.01 300.14,48 276.86,48 276.8,48.01 276.76,48.04 274.23,50.57 274.21,50.6 274.2,50.64 274.2,64.55 272.43,66.32 272.41,66.35 272.4,66.39 ; 3 cut-outs
P12V on CONDUCTIVE4: 274.18,76.82 274.21,76.89 274.28,76.92 300.33,76.92 300.37,76.91 300.4,76.89 301.87,75.42 301.89,75.39 301.9,75.35 301.9,49.74 301.89,49.7 301.87,49.67 300.22,48.02 300.19,48 300.15,47.99 276.82,47.99 276.78,48 276.75,48.02 274.21,50.56 274.19,50.59 274.18,50.63 ; 1 cut-out
VCC5R0_2 on CONDUCTIVE4: 231.74,12.92 231.76,13 231.83,13.06 231.98,13.13 235.74,16.89 235.82,16.95 235.92,16.97 237.81,16.97 238.03,17.03 238.09,17.01 238.14,16.96 238.32,16.72 238.14,16.48 238.09,16.42 238.03,16.4 237.81,16.47 236.02,16.47 232.33,12.77 232.26,12.62 232.2,12.56 232.12,12.54 232.08,12.54 231.79,12.59 231.75,12.88
VCC12R0_1 on BOTTOM (solid shape): 90.57,70.1 91.06,69.88 91.7,68.89 91.63,68.27 91.01,68.2 90.02,68.84 89.8,69.33 90.16,69.74
VCC12R0_1 on TOP: 89.73,69.73 89.75,69.78 90.18,70.72 90.18,71.87 89.42,72.62 89.37,72.7 89.35,72.8 89.35,73.2 89.32,73.23 89.27,73.31 89.25,73.4 89.25,73.6 89.27,73.69 89.32,73.77 89.35,73.8 89.35,74.72 89,75.07 88.94,75.15 88.92,75.25 88.97,75.39 89.08,75.48 89.17,75.5 89.25,75.49 89.31,75.46 89.35,75.43 89.78,75 89.83,74.92 89.85,74.83 89.85,73.8 89.88,73.77 89.93,73.69 89.95,73.6 89.95,73.4 89.93,73.31 89.88,73.23 89.85,73.2 89.85,72.9 90.61,72.15 90.66,72.06 90.68,71.97 90.68,70.72 91.11,69.78 91.13,69.73 91.14,69.68 90.94,69.43 90.66,69.56 90.48,69.97 90.38,69.97 90.2,69.56 89.92,69.43 89.73,69.68
VCC12R0_1 on TOP: 140.25,55.98 140.26,56.07 140.28,56.16 140.52,56.65 140.53,56.68 140.85,57.01 140.89,57.03 140.92,57.05 140.96,57.05 144.26,57.05 144.62,57.16 144.79,57.1 144.77,56.91 144.75,56.9 144.77,56.89 144.79,56.7 144.62,56.64 144.26,56.75 141.02,56.75 140.84,56.57 141.03,56.16 141.06,56.07 141.07,55.98 141.07,55.26 140.66,54.84 140.25,55.26
VCC12R0_1 on TOP: 144.45,45.5 143.6,46.35 142,46.35 141.9,46.37 141.82,46.42 140.48,47.77 140.43,47.85 140.41,47.94 140.41,48.7 140.25,49.3 140.25,49.35 140.25,49.76 139.72,49.99 139.33,49.99 139.1,49.76 138.91,49.48 138.89,49.45 138.77,49.41 138.66,49.48 138.64,49.52 138.62,49.53 138.54,49.62 138.56,49.75 138.58,49.77 138.6,49.79 138.88,49.97 139.16,50.25 139.2,50.28 139.23,50.29 139.27,50.29 139.72,50.29 140.25,50.52 140.33,50.55 140.41,50.55 140.66,50.55 140.95,50.43 141.07,50.14 141.07,49.35 141.07,49.3 140.91,48.7 140.91,48.05 142.1,46.85 143.7,46.85 143.8,46.83 143.88,46.78 144.88,45.78 144.93,45.7 144.95,45.6 144.95,44.9 144.7,44.65 144.45,44.9
VCC12R0_1 on CONDUCTIVE4: outline of 155 points within 123.97,5.26 208.7,97.3
VCC12R0_2 on CONDUCTIVE3: 227.95,60.99 227.8,61.34 227.8,64.19 225.29,66.7 221.85,66.7 221.5,66.85 221.35,67.2 221.35,70.65 221.39,70.84 221.5,71 225.65,75.16 225.65,84.89 224.5,86.05 224.39,86.21 224.35,86.4 224.35,90.45 224.39,90.64 224.5,90.8 226.15,92.46 226.51,92.61 226.86,92.46 227.01,92.11 226.86,91.75 225.35,90.24 225.35,86.61 226.5,85.45 226.61,85.29 226.65,85.1 226.65,74.95 226.61,74.76 226.5,74.6 222.35,70.44 222.35,68.66 223.31,67.7 225.5,67.7 225.69,67.66 225.85,67.55 228.65,64.75 228.76,64.59 228.8,64.4 228.8,61.34 228.65,60.99 228.3,60.84
VCC12R0_2 on CONDUCTIVE3: 230.28,100.37 230.78,100.87 231.28,100.37 231.28,93.18 230.78,92.68 230.28,93.18
VCC12R0_2 on CONDUCTIVE3: 237.45,14.9 237.26,14.94 237.1,15.05 236.84,15.3 230.8,15.3 230.61,15.34 230.45,15.45 223.75,22.15 223.64,22.31 223.6,22.5 223.6,41.79 223.75,42.14 224.1,42.29 224.45,42.14 224.6,41.79 224.6,22.71 231.01,16.3 237.05,16.3 237.24,16.26 237.4,16.15 237.66,15.9 242.76,15.9 243.02,16.15 243.72,16.15 243.72,15.45 243.32,15.05 243.16,14.94 242.97,14.9
$BN000001 on TOP: 165.62,61.05 165.56,61.06 165.52,61.09 165.03,61.58 165,61.62 164.99,61.68 164.99,63.83 165,63.89 165.03,63.93 165.31,64.21 165.35,64.24 165.41,64.25 167.39,64.25 167.45,64.24 167.49,64.21 167.75,63.95 167.78,63.91 167.79,63.85 167.79,61.63 167.78,61.57 167.75,61.53 167.31,61.09 167.27,61.06 167.21,61.05
$BN000001 on TOP: 189.25,20.38 188.25,21.38 189.25,22.38 190.42,22.38 194.49,26.46 194.71,26.62 194.96,26.72 195.08,26.74 195.2,26.75 203.45,26.75 204.45,25.75 203.45,24.75 195.61,24.75 191.54,20.67 191.42,20.57 191.28,20.49 191.06,20.41 190.83,20.38
$BN000001 on TOP: 134.42,61.05 134.36,61.06 134.32,61.09 133.83,61.58 133.8,61.62 133.79,61.68 133.79,63.83 133.8,63.89 133.83,63.93 134.11,64.21 134.15,64.24 134.21,64.25 136.19,64.25 136.25,64.24 136.29,64.21 136.55,63.95 136.58,63.91 136.59,63.85 136.59,61.63 136.58,61.57 136.55,61.53 136.11,61.09 136.07,61.06 136.01,61.05
$BN000001 on TOP: 168.91,2.05 168.8,2.09 168.76,2.2 168.76,2.75 168.77,2.8 168.8,2.85 169.78,3.83 169.83,3.86 169.88,3.87 171.67,3.87 171.73,3.86 171.78,3.83 172.42,3.19 172.45,3.14 172.46,3.09 172.46,2.2 172.42,2.09 172.31,2.05
$BN000001 on BOTTOM: outline of 209 points within 127.48,3.27 197.4,64.25
$BN000001 on BOTTOM: 148.8,8.36 148.81,8.51 148.82,8.53 148.85,8.55 148.84,8.56 148.82,8.75 148.99,8.81 149.34,8.68 149.42,8.68 149.73,8.72 150.96,8.72 150.99,8.72 151.27,8.68 151.41,8.68 153.25,10.51 153.25,10.53 153.18,10.79 153.18,10.85 153.18,11.03 153.24,11.18 153.4,11.25 153.58,11.25 153.63,11.24 153.95,11.18 155.33,11.18 155.51,11.45 155.59,11.52 155.7,11.55 155.88,11.55 155.93,11.54 156.14,11.5 157.22,11.5 157.9,11.8 157.99,11.81 158.65,11.81 159.11,11.35 158.65,10.89 157.99,10.89 157.9,10.9 157.28,11.18 156.25,11.18 155.93,11.11 155.88,11.1 155.77,11.1 155.54,10.95 155.47,10.89 155.43,10.88 155.4,10.88 153.95,10.88 153.55,10.53 153.55,10.45 153.54,10.39 151.58,8.42 151.54,8.39 151.51,8.38 151.47,8.38 151.27,8.38 150.96,8.32 149.73,8.32 149.7,8.33 149.42,8.38 149.33,8.38 148.97,8.28 148.93,8.28
$BN000001 on BOTTOM: 197.42,17.61 197.56,17.29 197.25,17.14 197.24,17.14 196.45,17.45 195.9,17.45 195.8,17.47 195.72,17.52 195.37,17.87 195.32,17.95 195.3,18.05 195.3,18.88 195.55,19.12 195.8,18.88 195.8,18.15 196,17.95 196.45,17.95 197.24,18.26 197.25,18.26 197.56,18.11 197.42,17.79 197.18,17.7
$BN000001 on BOTTOM: 195.3,19.95 195.32,20.05 195.37,20.13 195.93,20.69 196.01,20.74 196.11,20.76 196.77,20.76 196.78,20.76 197.91,20.76 197.98,20.76 198.04,20.74 198.68,20.55 199.4,20.55 200.38,21.54 200.38,21.91 200.18,22.61 200.17,22.68 200.17,23.01 200.63,23.47 201.09,23.01 201.09,22.68 201.09,22.61 201.07,22.55 200.88,21.91 200.88,21.43 200.86,21.34 200.81,21.26 199.68,20.12 199.6,20.07 199.5,20.05 198.68,20.05 198.04,19.86 197.98,19.84 197.91,19.84 196.78,19.84 196.72,19.84 196.65,19.86 196.19,20 195.95,20 195.8,19.85 195.8,19.73 195.55,19.48 195.3,19.73
$BN000001 on BOTTOM: 203.19,25.05 203.14,25.07 202.29,25.46 202.12,25.46 201.48,25.27 201.42,25.25 201.35,25.25 199.91,25.25 199.85,25.25 199.78,25.27 199.17,25.45 196.44,25.45 195.8,25.26 195.73,25.24 195.67,25.24 194.95,25.24 194.49,25.7 194.95,26.16 195.67,26.16 195.73,26.16 195.8,26.14 196.41,25.96 199.14,25.96 199.78,26.15 199.85,26.16 199.91,26.17 201.35,26.17 201.42,26.16 201.48,26.15 201.99,26 202.2,26 203.14,26.43 203.19,26.45 203.25,26.45 203.49,26.26 203.36,25.98 203.31,25.96 203.45,25.96 203.7,25.71 203.45,25.46 203.43,25.46 203.47,25.19 203.25,25.04
$BN000001 on BOTTOM: 158.65,13.59 158.19,14.05 158.65,14.51 159.31,14.51 159.4,14.5 160.08,14.2 160.67,14.2 161.35,14.5 161.44,14.51 162.1,14.51 162.56,14.05 162.1,13.59 161.44,13.59 161.35,13.6 160.67,13.9 160.08,13.9 159.4,13.6 159.31,13.59
$BN000001 on BOTTOM: 162.1,16.29 161.64,16.75 162.1,17.21 162.76,17.21 162.85,17.2 163.53,16.9 164.67,16.9 165.35,17.2 165.44,17.21 166.1,17.21 166.56,16.75 166.1,16.29 165.44,16.29 165.35,16.3 164.67,16.6 163.53,16.6 162.85,16.3 162.76,16.29
$BN000001 on CONDUCTIVE4: 157.79,32.6 157.75,32.61 157.72,32.63 157.54,32.81 138.69,32.81 137.73,33 136.92,33.54 136,34.46 124.94,34.46 123.98,34.65 123.17,35.19 118.33,40.03 118.24,40.13 118.15,40.23 99.53,58.85 98.99,59.66 98.8,60.62 98.8,78.64 97.18,80.26 96.92,80.57 96.71,80.91 96.52,81.45 96.45,82.03 96.45,120.6 96.46,120.85 96.5,121.1 96.5,132.2 96.53,132.27 96.6,132.3 102.9,132.3 103.05,132.26 103.16,132.15 103.2,132 103.2,120.62 103.19,120.58 103.17,120.55 101.45,118.83 101.45,83.06 103.07,81.45 103.61,80.64 103.8,79.68 103.8,61.66 122.91,42.55 123,42.45 123.09,42.34 125.98,39.46 137.04,39.46 138,39.27 138.81,38.73 139.73,37.81 157.51,37.81 157.53,37.83 157.77,38.07 157.8,38.09 157.84,38.1 162.26,38.1 162.3,38.09 162.33,38.07 163.52,36.88 163.54,36.85 163.55,36.81 163.55,33.94 163.54,33.9 163.52,33.87 162.28,32.63 162.25,32.61 162.21,32.6
$BN000002 on TOP: 123.39,122.67 123.41,122.81 123.46,122.95 123.74,123.47 123.74,123.78 123.46,124.3 123.41,124.44 123.39,124.58 123.39,124.85 123.41,124.99 123.46,125.13 123.84,125.85 123.84,126.04 123.86,126.1 124.19,126.46 124.23,126.48 124.27,126.5 124.3,126.5 124.44,126.5 124.82,126.61 124.86,126.62 125,126.53 124.97,126.36 124.95,126.35 124.97,126.34 124.99,126.15 124.82,126.09 124.44,126.2 124.36,126.2 124.14,125.98 124.14,125.85 124.58,124.99 124.59,124.85 124.59,124.58 124.58,124.44 124.52,124.3 124.24,123.78 124.24,123.47 124.52,122.95 124.58,122.81 124.59,122.67 124.59,122.4 123.99,121.8 123.39,122.4
$BN000002 on BOTTOM: 123.22,125.51 122.76,125.97 123.22,126.43 123.61,126.43 123.71,126.42 124.38,126.12 124.46,126.12 124.47,126.13 124.66,126.48 124.71,126.54 124.79,126.56 124.81,126.56 124.83,126.58 124.9,126.62 124.98,126.61 125.36,126.5 125.84,126.5 126.22,126.61 126.28,126.62 126.33,126.6 126.4,126.53 126.41,126.43 126.39,126.39 126.35,126.35 126.37,126.34 126.39,126.31 126.41,126.28 126.39,126.14 126.26,126.08 126.22,126.09 125.84,126.2 125.36,126.2 125.01,126.09 124.68,125.92 124.63,125.87 124.58,125.84 124.52,125.82 124.38,125.82 123.71,125.52 123.61,125.51
$BN000002 on BOTTOM: 148.86,7.43 148.86,7.46 148.79,7.47 148.74,7.5 148.7,7.55 148.69,7.61 148.71,7.69 148.77,7.74 149.1,7.91 149.17,7.98 149.22,8.01 149.28,8.03 149.57,8.03 149.88,8.07 150.66,8.07 150.72,8.06 150.77,8.03 151.96,8.03 154.11,10.17 154.16,10.2 154.22,10.21 156.79,10.21 156.85,10.2 157.26,9.81 157.49,9.66 158.46,9.66 158.53,9.67 158.6,9.66 158.61,9.65 159.26,9.65 159.96,9.88 160.03,9.89 160.45,9.89 160.91,9.43 160.45,8.97 160.03,8.97 159.96,8.98 159.89,8.99 159.26,9.21 158.54,9.21 158.5,9.21 157.42,9.21 157.31,9.24 157.05,9.59 156.73,9.91 154.28,9.91 152.13,7.77 152.08,7.74 152.03,7.72 150.77,7.72 150.72,7.69 150.66,7.67 149.88,7.67 149.85,7.68 149.57,7.72 149.34,7.72 149.31,7.7 149.14,7.37 149.12,7.34 149.09,7.32 148.96,7.3 148.87,7.41
$BN000002 on BOTTOM: 160.3,3.91 160.3,5.69 160,6.37 159.99,6.46 159.99,6.73 160.45,7.19 160.91,6.73 160.91,6.46 160.9,6.37 160.87,6.27 160.6,5.69 160.6,3.91 160.71,3.53 160.72,3.49 160.63,3.35 160.46,3.38 160.45,3.4 160.44,3.38 160.25,3.36 160.19,3.53
CONN002 on TOP: outline of 83 points within 141.13,77.74 149.77,89.44
CONN002 on TOP: 150.7,79.49 150.24,79.95 150.7,80.41 151.09,80.41 151.2,80.4 151.3,80.36 151.64,80.19 151.83,80.19 152.14,80.5 152.16,80.52 152.68,80.76 152.76,80.79 152.85,80.8 152.97,80.8 153.38,80.4 152.97,80 152.85,80 152.76,80.01 152.68,80.04 152.48,80.13 152.19,80.13 151.91,79.84 151.87,79.82 151.82,79.8 151.2,79.5 151.09,79.49
CONN002 on TOP: 180.75,79.2 184.75,79.2
CONN002 on TOP: 158.15,81.2 157.89,81.7 157.04,82.55 156.63,82.55 156.11,82.29 156.01,82.25 155.9,82.24 155.65,82.24 155.19,82.7 155.65,83.16 155.9,83.16 156.01,83.15 156.11,83.11 156.63,82.85 157.1,82.85 157.16,82.84 158.08,81.93 159.1,81.71 159.25,81.33 159.25,80.67 158.7,80.12 158.15,80.67
CONN002 on TOP: outline of 84 points within 145.45,81.43 154.63,95.65
CONN002 on TOP, BOTTOM: 164.6,86.24 164.54,86.25 164.5,86.28 164.01,86.77 163.98,86.81 163.97,86.87 163.97,89.02 163.98,89.08 164.01,89.12 164.29,89.4 164.33,89.43 164.39,89.44 166.37,89.44 166.43,89.43 166.47,89.4 166.73,89.14 166.76,89.1 166.77,89.04 166.77,86.82 166.76,86.76 166.73,86.72 166.29,86.28 166.25,86.25 166.19,86.24
CONN002 on BOTTOM: 152.64,86.24 152.58,86.25 152.54,86.28 152.05,86.77 152.02,86.81 152.01,86.87 152.01,89.02 152.02,89.08 152.05,89.12 152.33,89.4 152.37,89.43 152.43,89.44 154.41,89.44 154.47,89.43 154.51,89.4 154.77,89.14 154.8,89.1 154.81,89.04 154.81,86.82 154.8,86.76 154.77,86.72 154.33,86.28 154.29,86.25 154.23,86.24
CONN002 on BOTTOM: 141.76,86.24 141.7,86.25 141.66,86.28 141.17,86.77 141.14,86.81 141.13,86.87 141.13,89.02 141.14,89.08 141.17,89.12 141.45,89.4 141.49,89.43 141.55,89.44 143.53,89.44 143.59,89.43 143.63,89.4 143.89,89.14 143.92,89.1 143.93,89.04 143.93,86.82 143.92,86.76 143.89,86.72 143.45,86.28 143.41,86.25 143.35,86.24
CONN002 on BOTTOM: 181.06,115 181,115.01 180.96,115.04 180.79,115.21 180.76,115.25 180.75,115.31 180.75,118.69 180.76,118.75 180.79,118.79 180.96,118.96 181,118.99 181.06,119 184.34,119 184.4,118.99 184.44,118.96 184.71,118.69 184.74,118.65 184.75,118.59 184.75,115.36 184.74,115.3 184.71,115.26 184.49,115.04 184.45,115.01 184.39,115
CONN002 on BOTTOM: 181.06,77.1 181,77.11 180.96,77.14 180.79,77.31 180.76,77.35 180.75,77.41 180.75,80.79 180.76,80.85 180.79,80.89 180.96,81.06 181,81.09 181.06,81.1 184.34,81.1 184.4,81.09 184.44,81.06 184.71,80.79 184.74,80.75 184.75,80.69 184.75,77.46 184.74,77.4 184.71,77.36 184.49,77.14 184.45,77.11 184.39,77.1
CONN002 on BOTTOM: 158.72,72.64 158.5,72.86 158.72,73.09 158.9,73.09 158.95,73.08 159.27,73.01 159.55,73.01 159.8,73.26 160.03,73.97 160.04,74 160.23,74.06 160.31,73.88 160.21,73.57 160.32,73.46 160.63,73.56 160.67,73.57 160.72,73.56 160.8,73.51 160.82,73.42 160.79,73.33 160.72,73.28 160.67,73.26 160.67,73.01 160.63,72.9 160.52,72.86 160.16,72.86 160.05,72.75 160.01,72.72 159.95,72.71 159.27,72.71 158.95,72.64 158.9,72.64
CONN002 on CONDUCTIVE4: 163.6,85 163.45,85.04 163.34,85.15 163.3,85.3 163.3,87.5 162.2,90.01 159.61,90.89 159.59,90.89 159.45,90.9 159.3,90.9 148.15,90.9 148.1,90.9 145.6,89.96 144.55,87.5 144.55,85.9 144.51,85.75 144.4,85.64 144.25,85.6 140.95,85.6 140.8,85.64 140.69,85.75 140.65,85.9 140.65,90.67 140.66,90.7 140.68,90.74 147.25,97.31 147.32,97.36 147.47,97.4 154.9,97.4 161.26,103.76 161.32,103.81 161.47,103.85 167.38,103.85 167.45,103.84 167.59,103.76 167.91,103.44 167.96,103.38 168,103.23 168,89.46 168,89.43 167.55,88.5 167.4,87.5 167.4,85.3 167.36,85.15 167.25,85.04 167.1,85
CONN003 on TOP: 153.07,116.5 153.08,116.55 153.15,116.88 153.15,116.91 153.07,116.99 152.76,116.99 152.38,116.88 152.34,116.87 152.3,116.86 151.55,116.86 151.28,117.14 151.55,117.42 152.3,117.42 152.34,117.41 152.38,117.4 152.76,117.29 153.07,117.29 153.15,117.37 153.15,119.24 152.17,120.22 151.82,120.41 151.75,120.58 151.89,120.69 151.91,120.69 151.91,120.71 152.02,120.85 152.19,120.78 152.38,120.43 153.44,119.36 153.45,119.3 153.45,116.88 153.52,116.55 153.53,116.5 153.53,116.33 153.3,116.1 153.07,116.33
CONN003 on TOP: 141.59,122.49 141.61,122.62 141.66,122.74 141.8,122.95 141.8,123.23 141.6,123.65 141.59,123.76 141.59,124.8 141.6,124.91 141.9,125.53 141.9,126 141.75,126.15 139.38,126.15 139.32,126.16 139.27,126.19 137.39,128.07 137.36,128.12 137.35,128.18 137.35,128.87 136.96,129.39 136.47,129.39 136.41,129.4 136.37,129.43 136.15,129.65 136.12,129.69 136.11,129.75 136.11,130.29 135.85,130.56 135.81,130.61 135.8,130.66 135.8,131.94 135.81,132 135.85,132.05 136.35,132.55 136.39,132.58 136.45,132.59 138.42,132.59 138.44,132.59 138.51,132.59 138.57,132.58 138.61,132.55 138.87,132.29 138.9,132.25 138.91,132.19 138.91,129.69 138.9,129.63 138.87,129.59 138.71,129.43 138.67,129.4 138.61,129.39 138.04,129.39 137.65,128.87 137.65,128.24 139.44,126.45 141.82,126.45 142.15,126.52 142.2,126.53 142.38,126.53 142.59,126.37 142.5,126.11 142.22,125.93 142.2,125.91 142.2,125.53 142.5,124.91 142.51,124.8 142.51,123.76 142.5,123.65 142.46,123.55 142.3,123.23 142.3,122.95 142.44,122.74 142.49,122.62 142.51,122.49 142.51,122.1 142.05,121.64 141.59,122.1
CONN003 on TOP: 159.81,129.39 159.75,129.4 159.71,129.43 159.49,129.65 159.46,129.69 159.45,129.75 159.45,132.17 159.46,132.23 159.49,132.27 159.77,132.55 159.81,132.58 159.87,132.59 161.85,132.59 161.91,132.58 161.95,132.55 162.21,132.29 162.24,132.25 162.25,132.19 162.25,129.69 162.24,129.63 162.21,129.59 162.05,129.43 162.01,129.4 161.95,129.39
CONN003 on TOP: 180.75,64.1 184.75,64.1
CONN003 on TOP: outline of 116 points within 143,114.33 155.4,132.59
CONN003 on TOP: 180.47,100.5 179.6,100.5 179.03,100.61 178.54,100.94 175.78,103.7 157.26,103.7 157.2,103.71 157.16,103.74 156.9,104 156.74,104.14 156.6,104.3 156.34,104.56 156.31,104.6 156.3,104.66 156.3,106.84 156.31,106.9 156.34,106.94 157.75,108.35 157.75,108.79 157.76,108.85 157.79,108.89 157.86,108.96 157.9,108.99 157.96,109 158.85,109 158.96,108.96 159,108.85 159,107.3 159.56,106.74 159.57,106.72 159.59,106.7 176.4,106.7 176.97,106.59 177.46,106.26 180.22,103.5 180.47,103.5 182.27,103.94 183.18,103.82 183.76,103.11 184.25,102 183.76,100.89 183.76,100.88 183.17,100.18 182.27,100.06
CONN003 on BOTTOM: 136.48,129.39 136.42,129.4 136.38,129.43 136.15,129.66 136.12,129.7 136.11,129.76 136.11,132.17 136.12,132.23 136.15,132.27 136.43,132.55 136.47,132.58 136.53,132.59 138.51,132.59 138.57,132.58 138.61,132.55 138.87,132.29 138.9,132.25 138.91,132.19 138.91,129.7 138.9,129.64 138.87,129.6 138.7,129.43 138.66,129.4 138.6,129.39
CONN003 on BOTTOM: 181.2,62.6 180.63,62.71 180.14,63.04 175.59,67.59 175.26,68.08 175.15,68.65 175.15,83.1 175.26,83.67 175.59,84.16 182.2,90.77 182.2,99.7 181.86,100.04 181.82,100.21 181.96,100.3 182.2,100.3 182.2,100.43 181.69,100.94 181.69,103.06 183.81,103.06 184.76,102.11 185.09,101.62 185.2,101.05 185.2,90.15 185.09,89.58 184.76,89.09 178.15,82.48 178.15,69.27 181.82,65.6 182.75,65.6 184.25,64.1 182.75,62.6
CONN003 on BOTTOM: 159.82,129.39 159.76,129.4 159.72,129.43 159.49,129.66 159.46,129.7 159.45,129.76 159.45,132.17 159.46,132.23 159.49,132.27 159.77,132.55 159.81,132.58 159.87,132.59 161.85,132.59 161.91,132.58 161.95,132.55 162.21,132.29 162.24,132.25 162.25,132.19 162.25,129.69 162.24,129.63 162.21,129.59 162.05,129.43 162.01,129.4 161.95,129.39
CONN003 on BOTTOM: 166.1,100.15 165.75,100.3 165.6,100.65 165.6,100.78 165.58,100.84 165.55,101 165.58,101.16 165.6,101.22 165.6,101.35 165.75,101.7 166.1,101.85 166.39,101.85 166.58,101.81 166.75,101.7 166.87,101.58 166.91,101.54 166.94,101.5 167.39,101.5 169.02,103.13 169.02,103.53 168.85,103.7 156.91,103.7 156.72,103.74 156.55,103.85 156.35,104.05 156.24,104.22 156.2,104.41 156.2,106.79 156.24,106.98 156.35,107.15 157.75,108.55 158.29,108.65 158.6,108.19 158.6,107.2 159.1,106.7 168.92,106.7 169.09,106.87 169.09,107.2 167.29,109 166.89,109 166.86,108.96 166.82,108.92 166.42,108.78 166.05,109 165.55,109.5 166.05,110 166.42,110.22 166.82,110.08 166.86,110.04 166.89,110 167.5,110 167.69,109.96 167.85,109.85 170.7,107.01 171.51,106.7 171.8,106.7 173.3,105.2 171.8,103.7 171.51,103.7 170.7,103.39 167.96,100.65 167.79,100.54 167.6,100.5 166.94,100.5 166.91,100.46 166.87,100.42 166.75,100.3 166.58,100.19 166.39,100.15
CONN003 on CONDUCTIVE3: outline of 85 points within 146.8,102.5 166.4,132.37
CONN004 on TOP: outline of 177 points within 251.6,52.51 303.5,131.18 ; 4 cut-outs
CONN004 on BOTTOM: outline of 189 points within 251.57,52.53 298.36,131.15 ; 5 cut-outs
CONN004 on CONDUCTIVE3: outline of 95 points within 251.6,52.55 298.95,131.2 ; 5 cut-outs
CONN004 on CONDUCTIVE4: outline of 93 points within 251.55,52.52 298.93,131.27 ; 5 cut-outs
CS on TOP: 259.02,7.75 258.77,8 259.02,8.25 260.5,8.25 260.95,8.7 260.95,10.9 260.5,11.35 259.02,11.35 258.85,11.42 258.77,11.6 258.77,12.81 258.79,12.91 258.85,12.99 259.62,13.76 259.62,17.07 259.42,17.27 259.03,17.27 258.63,17.23 258.61,17.23 258.43,17.31 258.39,17.5 258.43,17.69 258.61,17.77 258.63,17.77 259.03,17.73 259.42,17.73 259.82,17.77 259.84,17.77 259.93,17.76 260,17.71 260.03,17.68 260.06,17.65 260.11,17.58 260.12,17.49 260.12,17.47 260.07,17.07 260.07,13.61 260.06,13.51 260,13.43 259.27,12.71 259.27,11.93 259.35,11.85 260.6,11.85 260.7,11.83 260.78,11.78 261.38,11.18 261.43,11.1 261.45,11 261.45,8.6 261.43,8.5 261.38,8.42 260.78,7.82 260.7,7.77 260.6,7.75
CS on TOP: 248.65,7.95 248.59,7.96 248.54,7.99 247.67,8.87 247.51,8.96 247.38,8.96 247.36,8.94 247.22,8.87 247.19,8.85 247.15,8.85 246.75,8.85 246.43,8.78 246.32,8.78 246.1,9 246.32,9.22 246.43,9.22 246.75,9.15 247.03,9.15 247.1,9.22 247.21,9.43 247.23,9.46 247.26,9.48 247.35,9.51 247.45,9.46 247.48,9.48 247.57,9.51 247.67,9.47 247.69,9.43 247.88,9.08 248.52,8.44 248.61,8.44 248.67,8.43 248.71,8.4 248.74,8.37 248.88,8.37 248.98,8.33 249.03,8.22 249.03,8.1 248.98,7.99 248.88,7.95
CS on TOP: 248.7,5.97 248.65,5.98 248.32,6.05 247.75,6.05 247.72,6.05 247.35,6.24 246.99,6.35 246.93,6.35 246.87,6.36 246.82,6.39 246.48,6.73 246.2,6.91 246.17,6.94 246.15,6.97 246.14,7.08 246.2,7.16 246.24,7.18 246.26,7.22 246.37,7.29 246.49,7.25 246.51,7.22 246.7,6.94 246.95,6.69 247.12,6.69 247.37,6.76 247.43,6.77 247.48,6.75 247.51,6.73 247.54,6.71 247.59,6.7 247.64,6.68 247.67,6.66 247.69,6.63 247.84,6.35 248.32,6.35 248.65,6.42 248.7,6.42 248.88,6.42 249.1,6.2 248.88,5.97
CS on BOTTOM: 256.97,9.35 256.91,9.39 256.82,9.41 256.76,9.47 256.59,9.8 256.31,10.07 256.03,10.07 255.72,10.03 255.06,10.03 254.86,10.22 255.06,10.43 255.72,10.43 255.75,10.42 256.03,10.38 256.38,10.38 256.43,10.36 256.8,10.01 257.1,9.86 257.46,9.75 257.62,9.75 257.95,9.82 258,9.82 258.18,9.82 258.4,9.6 258.18,9.38 258,9.38 257.95,9.38 257.62,9.45 257.46,9.45 257.08,9.34 257.04,9.33
CS on BOTTOM: 250.81,9.51 250.76,9.57 250.59,9.9 250.41,10.07 250.24,10.07 249.93,10.03 248.75,10.03 248.71,10.03 248.43,10.07 247.95,10.07 247.92,10.08 247.89,10.09 247.87,10.1 247.84,10.12 247.64,10.25 247.52,10.25 247.47,10.26 247.15,10.32 246.8,10.32 246.74,10.34 246.69,10.37 246.56,10.5 246.28,10.69 246.25,10.71 246.22,10.74 246.21,10.85 246.28,10.94 246.32,10.96 246.34,11 246.45,11.07 246.57,11.02 246.59,11 246.77,10.72 246.86,10.62 247.15,10.62 247.47,10.69 247.52,10.7 247.7,10.7 247.81,10.67 247.89,10.59 248.03,10.38 248.43,10.38 248.75,10.43 249.93,10.43 249.96,10.42 250.24,10.38 250.47,10.38 250.53,10.36 250.8,10.11 251.13,9.94 251.16,9.92 251.18,9.89 251.2,9.76 251.09,9.67 251.07,9.66 251.04,9.66 251.04,9.63 251.03,9.6 250.98,9.52 250.89,9.49
CS on BOTTOM: 243.79,11.98 243.6,12.26 243.06,12.8 241.23,12.8 240.88,12.69 240.7,12.76 240.72,12.94 240.74,12.95 240.72,12.97 240.7,13.15 240.88,13.22 241.23,13.1 243.12,13.1 243.18,13.09 243.23,13.06 243.82,12.47 244.1,12.29 244.12,12.27 244.14,12.25 244.16,12.12 244.08,12.03 244.06,12.02 244.04,11.98 243.93,11.91 243.81,11.95
CS on BOTTOM: 256.89,8.06 256.89,8.09 256.88,8.09 256.78,8.14 256.73,8.24 256.73,8.27 256.74,8.29 256.77,8.39 256.77,8.59 255.94,9.42 255.66,9.38 255.06,9.38 254.86,9.57 255.06,9.78 255.66,9.78 255.69,9.77 255.97,9.72 256,9.72 256.06,9.71 257.11,8.68 257.13,8.65 257.14,8.62 257.21,8.42 257.46,8.35 257.62,8.35 257.95,8.42 258,8.43 258.18,8.43 258.4,8.2 258.18,7.97 258,7.97 257.95,7.98 257.62,8.05 257.46,8.05 257.08,7.94 256.98,7.94 256.91,8
CS on BOTTOM: 255.06,15.22 254.86,15.43 255.06,15.62 255.72,15.62 255.76,15.62 256.04,15.57 256.06,15.57 256.97,16.48 257,16.5 257.03,16.52 257.27,16.59 257.3,16.6 257.33,16.6 257.4,16.6 257.62,16.38 257.4,16.15 257.33,16.15 257.3,16.15 257.27,16.16 257.12,16.21 256.23,15.32 256.18,15.29 256.12,15.28 256.04,15.28 255.72,15.22
CS on BOTTOM: 246.1,9.3 246.17,9.46 246.32,9.53 246.5,9.53 246.55,9.52 246.88,9.45 246.99,9.45 247.35,9.56 247.66,9.71 247.69,9.72 247.72,9.72 248.27,9.72 248.58,9.78 249.34,9.78 249.54,9.57 249.34,9.38 248.58,9.38 248.55,9.38 248.27,9.43 247.82,9.43 247.7,9.18 247.67,9.15 247.65,9.12 247.59,9.1 247.54,9.1 247.47,9.04 247.37,9.04 246.99,9.15 246.88,9.15 246.76,9.13 246.55,8.91 246.55,7.9 246.32,7.67 246.1,7.9
